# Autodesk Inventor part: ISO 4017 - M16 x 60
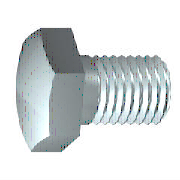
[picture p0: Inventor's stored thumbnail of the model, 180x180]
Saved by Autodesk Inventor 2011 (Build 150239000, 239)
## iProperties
IsCustomPart: 0
Created: 2010-02
Part Number: ISO 4017 - M16 x 60
Material: Stainless Steel, 440C
Description: Hexagon head screws
Document SubType Name: Modeling
Standard: ISO 4017
Designer: 129877
Standard Revision: Third edition 1999-08-15
Standards Organization: ISO
Language: en-US
Size Designation: M16 x 60
Categories: <MemberInstance><Categories><Category DisplayName="Fasteners" InternalName="e4da775c-781d-43d5-af7c-5136215cf5a6" Mnemonic="FSTN"><Category DisplayName="Bolts"
Density: 7.75 g/cm^3
Mass: 131.129 g
Surface Area: 47.7353 cm^2
Volume: 16.9199 cm^3
Author: 129877
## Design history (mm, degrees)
body "Solid1"
workplane "Work Plane1"
revolve "Body" stored, may be unused: angle "d12" = 90 deg
sketch "Sketch2"
  geometry: L1 (0, 13.856)-(12, 6.928); L2 (12, 6.928)-(12, -6.928); L3 (12, -6.928)-(0, -13.856); L4 (0, -13.856)-(-12, -6.928); L5 (-12, -6.928)-(-12, 6.928); L6 (-12, 6.928)-(0, 13.856); 2 further points
  constraints: 12 end point, 1 coincident, 1 vertical, 11 other
  dimensions: "d11" = 24 distance between parallel lines of L5 L2 (= SW)
extrude "Head" join sketch "Sketch2" distance "d3" = 9.2 (= KOH - SD); taper "d4" = 0 deg
revolve "Chamfer1" stored, may be unused: angle "d21" = 90 deg
feature "Thread" dims "d15" = 54 (= GEL), "d16" = 0
chamfer "Chamfer2" distance "d6" = 1.2269 (= -0.5 x SPD + 0.5 x GD); stored, may be unused: second distance "d7" = 1.227 (computed from GUL), angle "d55" = 45 deg
sketch "Sketch1"
  geometry: L1 (0, 11.245)-(0, 8); L2 (6, 8)-(60, 8); L3 (60, 8)-(60, 0); L4 (60, 0)-(-0.8, 0); L5 (-12.96, 0)-(72.16, 0) reference; L6 (-0.8, 0)-(-0.8, 11.245); L7 (-0.8, 11.245)-(0, 11.245); L8 (6, 8)-(4.773, 8); L9 (4.773, 8)-(0, 8); L10 (0, -2.249)-(0, 13.494) reference
  constraints: 16 end point, 2 collinear, 2 perpendicular, 1 parallel
  dimensions: "d0" = 60 distance between parallel lines of L3 L1 (= NLG); "d1" = 54 distance from line of L2.start L3 (= GEL); "d2" = 16 diameter of L2 L4 (= GD); "d9" = 0.8001 distance between parallel lines of L6 L1 (computed from SD); "d10" = 22.49 diameter of L7 L4 (= SD2); "d13" = 1.227 distance of L2.start L8.end (computed from GAL); "d14" = 16 diameter of L9 L4 (= BDM)
sketch "Sketch4"
  geometry: L1 (-10, 12)-(-10, 13.856); L2 (-10, 13.856)-(-8.928, 13.856); L3 (-8.928, 13.856)-(-10, 12); L4 (-11.84, 0)-(1.04, 0) reference; L5 (-0.8, 13.856)-(-10, 13.856) reference; L6 (-10, 6.928)-(-10, 13.856) reference
  constraints: 6 end point, 2 collinear, 1 perpendicular, 1 vertical
  dimensions: "d5" = 30 deg angle of L3 L1 (= ANG1); "d19" = 24 diameter of L1.start L4 (= SW0)
other parameters: "NLG" = 60 [user parameter; used in 1 equation term], "GD" = 16 (= NND) [user parameter; used in 2 equation terms], "BDM" = 16 (= NND) [user parameter; used in 1 equation term], "KOH" = 10 [user parameter; used in 1 equation term], "GEL" = 54 [user parameter; used in 2 equation terms], "SW" = 24 [user parameter; used in 2 equation terms], "SW0" = 24 (= SW) [user parameter; used in 1 equation term], "SPD" = 13.5462 (= NND - 1.2269 x PTC) [user parameter; used in 1 equation term], "SD2" = 22.49 [user parameter; used in 2 equation terms], "SD" = 0.8 [user parameter; used in 2 equation terms], "ANG1" = 30 deg [user parameter; used in 1 equation term], "GAL" = 1.2269 (= 0.61345 x PTC) [user parameter; used in 1 equation term], "GUL" = 1.2269 (= 0.61345 x PTC) [user parameter; used in 1 equation term], "d8" = 0, "RR" = 0.6 [user parameter], "d57" = 0, "d58" = 0, "TPU" = 5 (computed from PTC) [user parameter], "GD1" = 13.5462 (= THREADDIA - 1.2269 x PTC) [user parameter], "THREADDIA" = 16 [user parameter; used in 1 equation term], "SDH" = 22.49 (= SD2) [user parameter], "SDHG" = 6 [user parameter], "TOA" = 30 deg [user parameter], "PTC" = 2 [user parameter; used in 5 equation terms], "NND" = 16 [user parameter; used in 3 equation terms], "E0" = 27.72 [user parameter]
